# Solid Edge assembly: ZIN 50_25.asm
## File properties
Title: Zylinder
Author: bmolnar
Template: iso metric assembly.asm
Last saved by: bmolnar
Revision: 12
Application: Solid Edge
Username: bmolnar
Dokumentum tartalom típus: 1
Document Number: ZIN 50/25
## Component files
Profilrohr.par
Kolbenstange.par
Kit_2.par
Kit_1.par
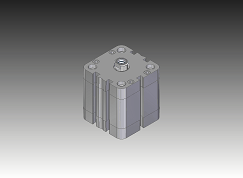
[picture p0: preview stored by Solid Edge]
